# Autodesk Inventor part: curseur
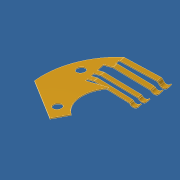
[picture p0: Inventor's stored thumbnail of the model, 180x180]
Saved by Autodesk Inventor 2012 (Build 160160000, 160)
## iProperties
Created: 2011-07
Part Number: curseur
Document SubType Name: Tôlerie
Designer: didierf
Density: 8.47 g/cm^3
Material: Laiton (jaune doux)
Mass: 0.0357038 g
Surface Area: 0.921068 cm^2
Volume: 0.00421532 cm^3
Sheet Metal Rule: Par défaut
Author: didierf
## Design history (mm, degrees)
sketch "Esquisse3"
  geometry: L1 (-14.379, 11.345)-(1.25, 18.566); L2 (1.25, 18.566)-(10.479, -1.409); L3 (10.479, -1.409)-(-5.149, -8.63); L4 (-5.149, -8.63)-(-14.379, 11.345); L5 (4.506, -11.411)-(4.506, -32.563); 1 other entity
  constraints: 2 end point, 1 vertical, 2 other
  dimensions: "d19" = 17.216 distance of L1.start L1.end; "d84" = 24.7991 deg angle of L5 L4
  node "Image2"
sketch "tracé"
  geometry: L1 (3.886, -3.147)-(6.941, 0.626); L2 (0, -41.976)-(0, 8.25); L3 (-3.534, -3.184)-(-5.423, -0.851); L4 (-5.774, -0.814)-(-6.941, 0.626); L5 (0, 0)-(-3.552, -3.519); C1 r 2.5 at (0, 0); C2 r 0.5 at (4.25, -0.7); C3 r 0.5 at (4.25, 5.1); C4 r 2.95 at (0, 0); C5 r 0.96 at (3, 4); A1 r 5 centre (0, 0) between (-3.552, -3.519) and (3.886, -3.147); A2 r 8.25 centre (0, 0) between (7.243, 3.95) and (-7.243, 3.95); A3 r 3 centre (-4.609, 2.514) between (-7.243, 3.95) and (-6.941, 0.626); A4 r 3 centre (4.609, 2.514) between (6.941, 0.626) and (7.243, 3.95); A5 r 0.25 centre (-3.728, -3.341) between (-3.552, -3.519) and (-3.534, -3.184); A6 r 0.25 centre (-5.617, -1.009) between (-5.423, -0.851) and (-5.774, -0.814); A7 r 7.95 centre (0, 0) between (7.603, 2.323) and (-7.603, 2.323); 1 further point
  constraints: 17 point on circle, 12 centre point, 10 end point, 9 tangent, 5 coincident, 1 parallel, 1 point on line, 1 vertical
  dimensions: "d53" = 10 diameter of A1; "d54" = 5 diameter of C1; "d57" = 8.25 radius of A2; "d60" = 6 diameter of A3; "d61" = 6 diameter of A4; "d66" = 78 deg angle of L1 L4; "d67" = 0.25 radius of A5; "d68" = 0.25 radius of A6; "d69" = 0.25 distance between parallel lines of L4 L3; "d70" = 3.5 distance of L4.start L5.end; "d71" = 39 deg angle of L1 L2 (derived); "d104" = 1 diameter of C2; "d105" = 1 diameter of C3; "d106" = 4.25 horizontal distance of C2.centre point (0, 0); "d107" = 0.7 vertical distance of C2.centre point (0, 0); "d108" = 5.8 distance of C2.centre C3.centre; "d109" = 4.25 horizontal distance of C3.centre point (0, 0) (derived); "d110" = 0.3 radial gap between concentric circles of A7 A2; "d114" = 5.9 diameter of C4; "d115" = 1.92 diameter of C5; "d117" = 3 distance from line of C5.centre L2; "d120" = 4 vertical distance of C5.centre point (0, 0)
sketch "piece_a_plat"
  geometry: L1 (1.033, 3.091)-(3.317, 3.6); L2 (3.317, 3.6)-(3.244, 3.926); L3 (3.244, 3.926)-(-1.948, 2.769); L4 (2.7, 6.366)-(-2.98, 5.101); L5 (-3.587, 6.707)-(1.418, 7.822); L6 (-2.489, 4.186)-(2.918, 5.39); L7 (1.642, 7.258)-(-3.457, 6.121); L8 (1.751, 6.77)-(-3.111, 5.686); L9 (1.751, 6.77)-(1.642, 7.258); L10 (-3.587, 6.707)-(-3.457, 6.121); L11 (-3.111, 5.686)-(-2.98, 5.101); L12 (3.135, 4.414)-(-2.056, 3.258); L13 (3.026, 4.902)-(-2.38, 3.698); L14 (1.277, 6.049)-(1.146, 6.635); L15 (1.037, 7.123)-(0.907, 7.709); L16 (-2.489, 4.186)-(-2.38, 3.698); L17 (-2.056, 3.258)-(-1.948, 2.769); L18 (2.918, 5.39)-(2.7, 6.366); L19 (2.57, 3.776)-(2.462, 4.264); L20 (2.353, 4.752)-(2.244, 5.24); L21 (3.317, 3.6)-(3.244, 3.926); L22 (3.135, 4.414)-(3.026, 4.902); L23 (7.51, 2.609)-(4.243, -2.596); L24 (4.243, -2.596)-(2.68, -1.616); L25 (1.033, 3.091)-(1.066, 2.942); L26 (-2.649, 6.916)-(-2.518, 6.331); L27 (-2.159, 5.898)-(-2.028, 5.313); L28 (-1.515, 4.403)-(-1.407, 3.915); L29 (-1.089, 3.473)-(-0.98, 2.985); L30 (-3.587, 6.707)-(-2.649, 6.916); L31 (-2.056, 3.258)-(-1.089, 3.473); L32 (-3.118, 6.812)-(-2.988, 6.226); L33 (-2.633, 5.793)-(-2.503, 5.207); L34 (-1.995, 4.296)-(-1.886, 3.808); L35 (-1.573, 3.365)-(-1.464, 2.877); C1 r 0.5 at (4.25, 5.1) reference; C2 r 0.5 at (4.25, 5.1); C3 r 0.5 at (4.25, -0.7) reference; C4 r 0.5 at (4.25, -0.7); A1 r 7.95 centre (0, 0) between (7.603, 2.323) and (-7.603, 2.323) reference; A2 r 7.95 centre (0, 0) between (7.51, 2.609) and (1.418, 7.822); A3 r 3.129 centre (0, 0) between (2.68, -1.616) and (1.066, 2.942); A4 r 3.129 centre (0, 0) between (-0.561, 3.079) and (-0.799, 3.025)
  constraints: 70 end point, 24 perpendicular, 24 point on line, 16 parallel, 7 point on circle, 5 centre point, 4 coincident, 3 concentric, 2 midpoint
  dimensions: "d145" = 0.6 distance of L5.start L7.end; "d146" = 0.6 distance of L8.end L4.end; "d147" = 0.5 distance of L6.start L13.end; "d148" = 0.5 distance of L12.end L3.end; "d222" = 1 distance between parallel lines of L6 L4; "d223" = 0.5 distance between parallel lines of L12 L13; "d224" = 0.5 distance between parallel lines of L7 L8
node "aplat"
feature "Pliage1patte1" dims "d150" = 0.1 (derived), "d151" = 0.05 (derived), "d152" = 0.2 (derived), "d153" = 0.1 (derived), "d154" = 3.42085, "d155" = 0.1 (derived), "Epaisseur" = 0.1, "JeuJointure" = 0.01
feature "Pliage1patte2" dims "d229" = 0.1 (derived), "d230" = 0.05 (derived), "d231" = 0.2 (derived), "d232" = 0.1 (derived), "d233" = 3.23759, "d234" = 0.1 (derived), "Epaisseur" = 0.1, "JeuJointure" = 0.01
sketch "Esquisse6"
  geometry: L1 (4.604, -0.5)-(4.604, 0) reference; L2 (4.604, 0)-(0, 0) reference; L3 (0, 0)-(0, -0.5) reference; L4 (0, -0.5)-(1.177, -0.5) reference; L5 (1.421, -0.5)-(4.604, -0.5) reference; L6 (1, 0)-(1, -0.5); A1 r 3.129 centre (1.299, -3.627) between (1.421, -0.5) and (1.177, -0.5) reference
  constraints: 2 end point, 2 point on line, 1 perpendicular
  dimensions: "d235" = 1 distance between parallel lines of L6 L3
feature "Pliage2patte1" sketch "Esquisse6" dims "d158" = 0.1 (derived), "d159" = 0.05 (derived), "d160" = 0.2 (derived), "d161" = 0.1 (derived), "d162" = 45 deg, "d163" = 0.1 (derived), "Epaisseur" = 0.1, "JeuJointure" = 0.01
sketch "Esquisse7"
  geometry: L1 (0, 0)-(0.943, 0) reference; L2 (0, 0.5)-(0, 0) reference; L3 (0.5, 0.5)-(0.5, 0); L4 (0.943, 0.5)-(0, 0.5) reference
  constraints: 2 end point, 2 point on line, 1 parallel
  dimensions: "d164" = 0.5 distance between parallel lines of L3 L2
feature "Pliage3patte1" sketch "Esquisse7" dims "d165" = 0.1 (derived), "d166" = 0.05 (derived), "d167" = 0.2 (derived), "d168" = 0.1 (derived), "d169" = 110 deg, "d170" = 0.4, "Epaisseur" = 0.1, "JeuJointure" = 0.01
sketch "Esquisse8"
  geometry: L1 (4.826, -0.5)-(4.826, 0) reference; L2 (4.826, 0)-(0, 0) reference; L3 (0, 0)-(0, -0.5) reference; L4 (0, -0.5)-(4.826, -0.5) reference; L5 (1, 0)-(1, -0.5)
  constraints: 2 end point, 2 point on line, 1 perpendicular
  dimensions: "d236" = 1 distance between parallel lines of L3 L5
feature "Pliage2patte2" sketch "Esquisse8" dims "d172" = 0.1 (derived), "d173" = 0.05 (derived), "d174" = 0.2 (derived), "d175" = 0.1 (derived), "d176" = 45 deg, "d177" = 0.1 (derived), "Epaisseur" = 0.1, "JeuJointure" = 0.01
sketch "Esquisse9"
  geometry: L1 (0.943, 0)-(0, 0) reference; L2 (0.943, 0.5)-(0.943, 0) reference; L3 (0, 0.5)-(0.943, 0.5) reference; L4 (0.443, 0)-(0.443, 0.5)
  constraints: 2 end point, 2 point on line, 1 perpendicular
  dimensions: "d237" = 0.5 distance between parallel lines of L2 L4
feature "Pliage3patte2" sketch "Esquisse9" dims "d179" = 0.1 (derived), "d180" = 0.05 (derived), "d181" = 0.2 (derived), "d182" = 0.1 (derived), "d183" = 110 deg, "d184" = 0.4, "Epaisseur" = 0.1, "JeuJointure" = 0.01
sketch "Esquisse10"
  geometry: L1 (-2.298, 6.061)-(-1.938, 5.581) reference; L2 (-6.177, 3.15)-(-5.817, 2.67); L3 (-2.763, 7.087)-(-2.403, 6.607) reference; L4 (-6.837, 4.03)-(-6.477, 3.55); L5 (-1.938, 5.581)-(-6.593, 2.088) reference; L6 (-6.282, 3.071)-(-2.298, 6.061) reference; L7 (-2.403, 6.607)-(-6.582, 3.471) reference; L8 (-6.865, 4.009)-(-2.763, 7.087) reference
  constraints: 4 end point, 4 point on line, 2 parallel, 1 collinear, 1 perpendicular
  dimensions: "d185" = 4.85 distance between parallel lines of L2 L1
feature "Pliage1patte3" dims "d186" = 0.1 (derived), "d187" = 0.05 (derived), "d188" = 0.2 (derived), "d189" = 0.1 (derived), "d190" = 3.23759, "d191" = 0.1 (derived), "Epaisseur" = 0.1, "JeuJointure" = 0.01
sketch "Esquisse11"
  geometry: L1 (4.827, 0.6)-(4.827, 0) reference; L2 (3.827, 0.6)-(3.827, 0)
  constraints: 2 end point, 1 parallel
  dimensions: "d192" = 1 distance between parallel lines of L2 L1
feature "Pliage2patte3" sketch "Esquisse11" dims "d193" = 0.1 (derived), "d194" = 0.05 (derived), "d195" = 0.2 (derived), "d196" = 0.1 (derived), "d197" = 45 deg, "d198" = 0.1 (derived), "Epaisseur" = 0.1, "JeuJointure" = 0.01
sketch "Esquisse12"
  geometry: L1 (0.943, 0.6)-(0.943, 0) reference; L2 (0.443, 0.6)-(0.443, 0)
  constraints: 2 end point, 1 parallel
  dimensions: "d199" = 0.5 distance between parallel lines of L2 L1
feature "Pliage3patte3" sketch "Esquisse12" dims "d200" = 0.1 (derived), "d201" = 0.05 (derived), "d202" = 0.2 (derived), "d203" = 0.1 (derived), "d204" = 110 deg, "d205" = 0.4, "Epaisseur" = 0.1, "JeuJointure" = 0.01
feature "Pliage1patte4" dims "d238" = 0.1 (derived), "d239" = 0.05 (derived), "d240" = 0.2 (derived), "d241" = 0.1 (derived), "d242" = 2.64417, "d243" = 0.1 (derived), "Epaisseur" = 0.1, "JeuJointure" = 0.01
sketch "Esquisse13"
  geometry: L1 (4.773, 0.6)-(4.773, 0); L2 (3.773, 0.6)-(3.773, 0); L3 (0, 0.6)-(0, 0) reference; L4 (5.074, 0)-(0, 0) reference; L5 (5.074, 0.6)-(5.074, 0) reference; L6 (0, 0.6)-(5.074, 0.6) reference
  constraints: 4 end point, 1 parallel
  dimensions: "d206" = 1 distance between parallel lines of L2 L1
feature "Pliage2patte4" sketch "Esquisse13" dims "d207" = 0.1 (derived), "d208" = 0.05 (derived), "d209" = 0.2 (derived), "d210" = 0.1 (derived), "d211" = 45 deg, "d212" = 0.1 (derived), "Epaisseur" = 0.1, "JeuJointure" = 0.01
sketch "Esquisse14"
  geometry: L1 (1.244, 0.6)-(1.244, 0) reference; L2 (0.744, 0.6)-(0.744, 0)
  constraints: 2 end point, 1 parallel
  dimensions: "d213" = 0.5 distance between parallel lines of L2 L1
feature "Pliage3patte4" sketch "Esquisse14" dims "d214" = 0.1 (derived), "d215" = 0.05 (derived), "d216" = 0.2 (derived), "d217" = 0.1 (derived), "d218" = 110 deg, "d219" = 0.4, "Epaisseur" = 0.1, "JeuJointure" = 0.01
node "Plan de construction5"
node "Solide1"
node "Corps solides"
node "Corps surfaciques"
feature "Plaque1" dims "Epaisseur" = 0.1
node "Boucle projetée1"
node "Boucle projetée2"
other parameters: "d52" = 78 deg, "d62" = 0.25, "d63" = 0.25, "RayonPli" = 0.1 (derived), "LargeurGrugeage" = 0.1 (derived), "ProfondeurGrugeage" = 0.05 (derived), "TailleGrugeage" = 0.4 (derived), "RestesMinimum" = 0.2 (derived), "Rayondetransition" = 0.1 (derived), "TailleRayonJacobi" = 0.1 (derived), "d149" = 0.1 (derived), "d228" = 1.55, "TailleJeu" = 0.1 (derived)
